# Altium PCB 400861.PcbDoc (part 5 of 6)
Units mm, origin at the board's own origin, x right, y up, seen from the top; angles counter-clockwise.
Board outline 145 x 63.5 mm, 8 copper layers (Top Side, Mid-Layer 1, Mid-Layer 2, Mid-Layer 3, Mid-Layer 4, Mid-Layer 5, Mid-Layer 6, Bottom Side), stack 1.529 mm thick; 284 components, 233 nets, 1158 pads, 3522 vias.
Unrouted connection lines stored in the file: 1.
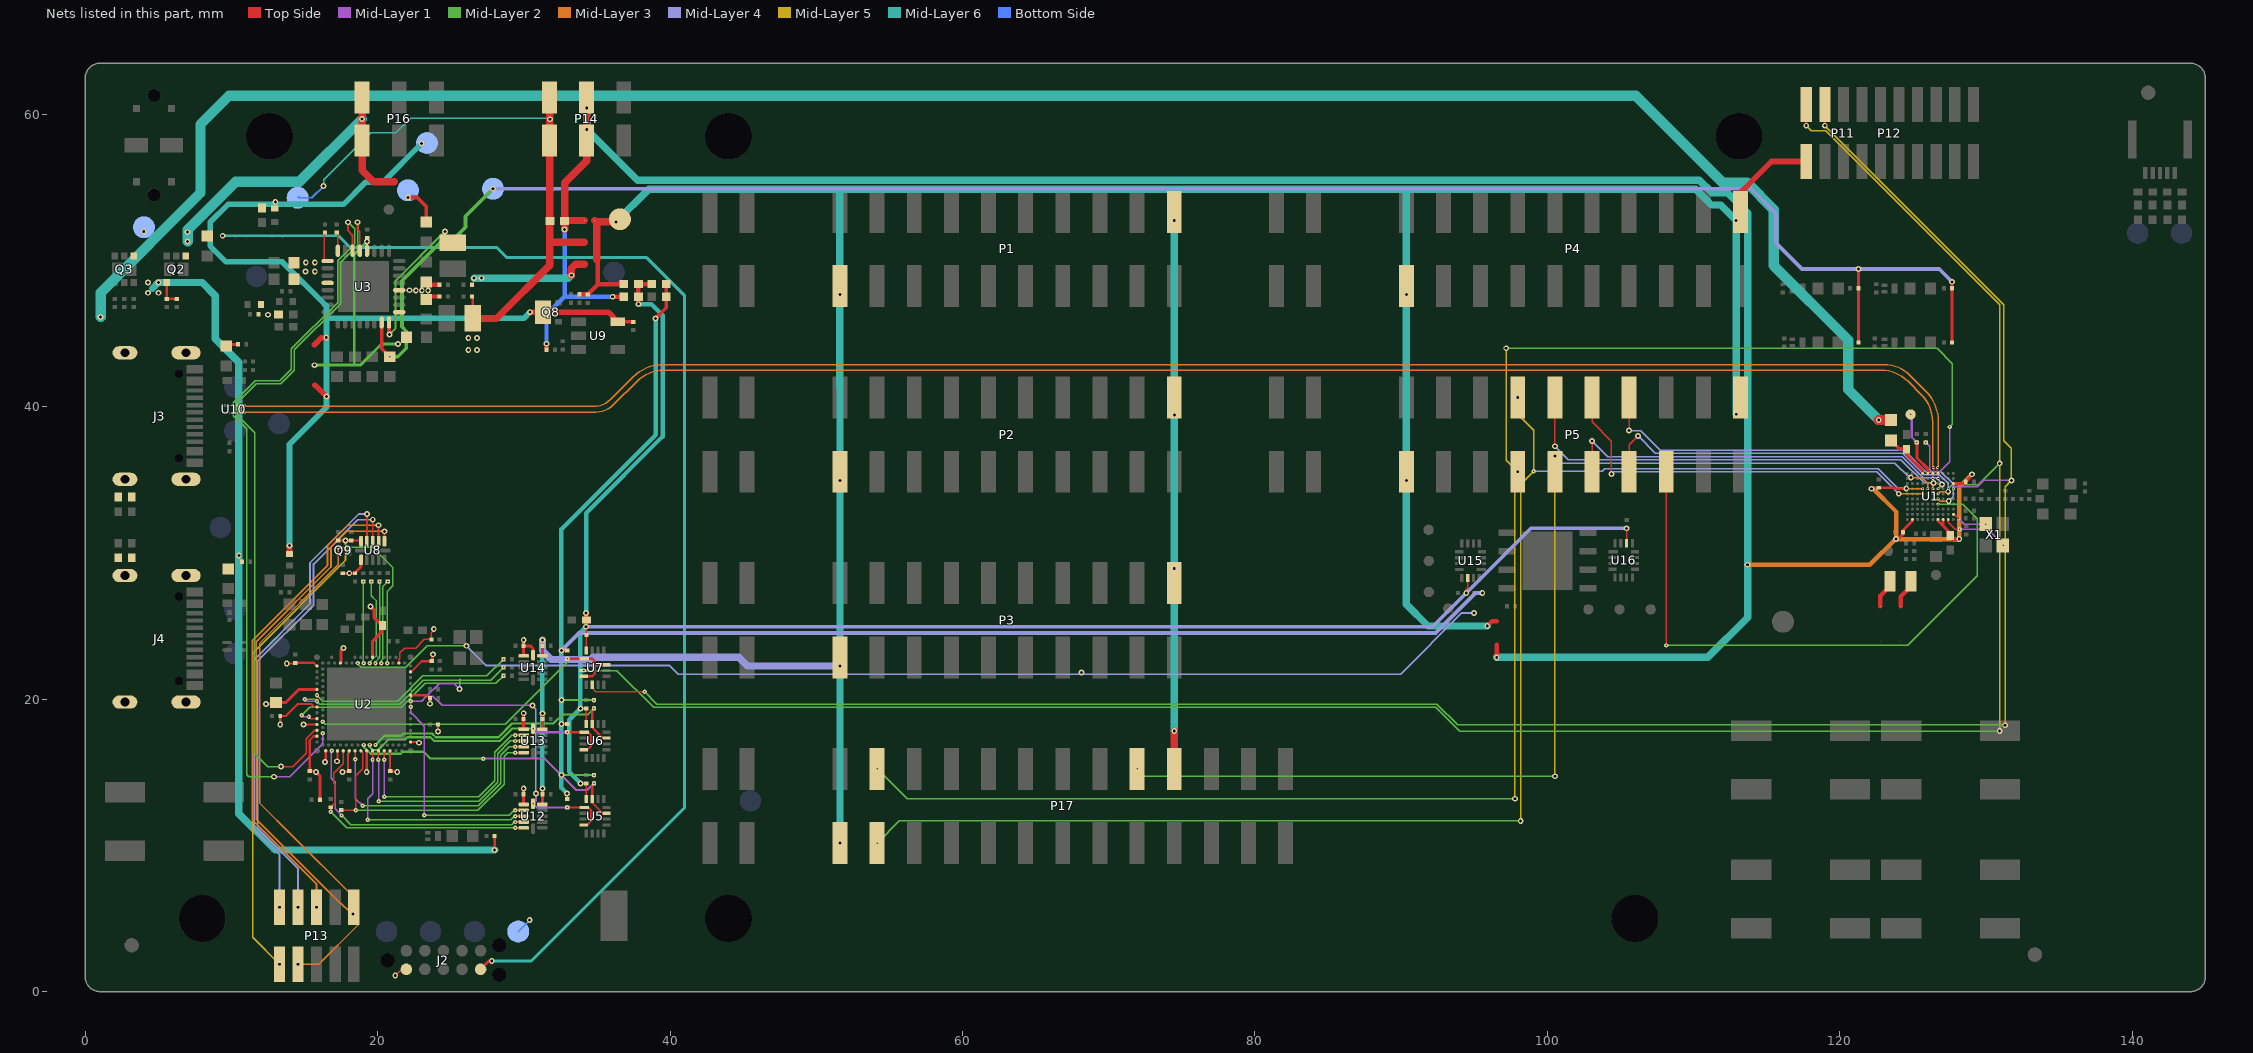
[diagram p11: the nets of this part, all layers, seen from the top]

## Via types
v1: diameter 0.4, hole 0.2, Top Side to Bottom Side, tented both sides, 2426 vias
v2: diameter 0.3, hole 0.1, Top Side to Mid-Layer 1, tented both sides, 299 vias
v3: diameter 0.4, hole 0.2, Mid-Layer 3 to Mid-Layer 4, tented both sides, 197 vias
v4: diameter 0.3, hole 0.1, Mid-Layer 1 to Mid-Layer 2, tented both sides, 197 vias
v5: diameter 0.3, hole 0.1, Mid-Layer 2 to Mid-Layer 3, tented both sides, 91 vias
v6: diameter 0.3, hole 0.1, Mid-Layer 4 to Mid-Layer 5, tented both sides, 81 vias
v7: diameter 0.3, hole 0.1, Mid-Layer 2 to Mid-Layer 3, 71 vias
v8: diameter 0.2, hole 0.1, Top Side to Mid-Layer 1, tented both sides, 64 vias
v9: diameter 0.2, hole 0.1, Mid-Layer 1 to Mid-Layer 2, tented both sides, 41 vias
v10: diameter 0.2, hole 0.1, Mid-Layer 2 to Mid-Layer 3, 19 vias
v11: diameter 0.2, hole 0.1, Mid-Layer 2 to Mid-Layer 3, tented both sides, 14 vias
v12: diameter 0.3, hole 0.1, Mid-Layer 5 to Mid-Layer 6, tented both sides, 12 vias
v13: diameter 0.2, hole 0.1, Mid-Layer 1 to Mid-Layer 2, 4 vias
v14: diameter 0.3, hole 0.1, Top Side to Mid-Layer 1, tented top, 3 vias
v15: diameter 0.2, hole 0.1, Top Side to Mid-Layer 1, tented top, 2 vias
v16: diameter 0.225, hole 0.1, Mid-Layer 1 to Mid-Layer 2, tented both sides, 1 vias

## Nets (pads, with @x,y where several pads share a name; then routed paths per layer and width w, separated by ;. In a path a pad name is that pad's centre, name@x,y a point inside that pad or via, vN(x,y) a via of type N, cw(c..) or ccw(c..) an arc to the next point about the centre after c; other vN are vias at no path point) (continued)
P3.04: P5.7 P17.4 U1.J4 | length 114.9
  Top Side w0.1: P17.4@54.16,15.24 v2(54.16,15.243)
  Mid-Layer 1 w0.1: v8(126.72,35.1) 126.72,35.464 127.512,36.256 v4(127.512,38.624)
  Mid-Layer 2 w0.1: v2(54.16,15.243) 56.208,13.195 v5(97.781,13.195) ; v5(97.185,44.006) 126.657,44.006 127.708,42.955 127.708,38.821 v4(127.512,38.624)
  Mid-Layer 5 w0.1: v5(97.185,44.006) 97.185,36.35 v6(97.975,35.56) 97.781,35.366 v5(97.781,13.195)
  other v2: 97.975,35.56
  other v3: 97.781,13.195 97.975,35.56 97.185,44.006
  other v4: 54.16,15.243 97.975,35.56
  other v5: 97.975,35.56
  other v6: 97.781,13.195 97.185,44.006
P3.05: P5.8 P17.3 U1.G7 | length 101.7
  Top Side w0.1: P17.3@54.16,10.16 v2(54.166,10.16)
  Mid-Layer 2 w0.1: v2(54.166,10.16) 55.681,11.675 v6(98.177,11.675)
  Mid-Layer 3 w0.1: v3(124.55,34.419) 124.569,34.4 v11(125.67,34.4)
  Mid-Layer 4 w0.1: v6(99.065,35.603) 103.761,35.603 103.911,35.752 122.648,35.752 123.981,34.419 v3(124.55,34.419)
  Mid-Layer 5 w0.1: v6(97.975,40.64) 97.975,39.485 99.065,38.395 v6(99.065,35.603) 98.177,34.715 v6(98.177,11.675)
  other v2: 97.975,40.64
  other v3: 98.177,11.675 97.975,40.64
  other v4: 54.166,10.16 97.975,40.64
  other v5: 98.177,11.675 97.975,40.64
  other v8: 125.67,34.4
  other v9: 125.67,34.4
P3.06: P5.9 P17.18 U1.G6 | length 77.4
  Top Side w0.1: P17.18@71.94,15.24 v2(71.94,15.242)
  Mid-Layer 2 w0.1: v2(71.94,15.242) 72.445,14.737 100.511,14.737 v5(100.515,14.733)
  Mid-Layer 3 w0.1: v3(124.858,35.157) 124.874,35.141 125.658,35.141 126.02,34.779 v8(126.02,34.4)
  Mid-Layer 4 w0.1: v3(100.515,36.645) 101.002,36.158 123.774,36.158 124.776,35.157 v3(124.858,35.157)
  Mid-Layer 5 w0.1: v5(100.515,14.733) v3(100.515,36.645)
  other v2: 100.515,36.645
  other v3: 100.515,14.733
  other v4: 71.94,15.242 100.515,36.645
  other v5: 100.515,36.645
  other v6: 100.515,14.733 100.515,36.645
  other v9: 126.02,34.4
  other v11: 126.02,34.4
P3.07: P5.10 U1.G5 | length 30.1
  Top Side w0.1: v1(100.513,37.306) 100.515,37.308 P5.10@100.515,40.05
  Mid-Layer 3 w0.1: v11(126.37,34.4) 126.37,34.749 v3(126.419,34.797)
  Mid-Layer 4 w0.1: v1(100.513,37.306) 101.44,36.38 124.18,36.38 125.762,34.797 v3(126.419,34.797)
  other v8: 126.37,34.4
  other v9: 126.37,34.4
P3.08: P5.11 U1.G4 | length 28.3
  Top Side w0.1: P5.11@103.055,34.97 v1@103.055,37.659
  Mid-Layer 3 w0.1: v8(126.72,34.4) 126.988,34.668 v3(126.988,34.691)
  Mid-Layer 4 w0.1: v1(103.055,37.659) 104.134,36.58 124.283,36.58 125.706,35.157 126.597,35.157 126.988,34.765 v3(126.988,34.691)
  other v9: 126.72,34.4
  other v11: 126.72,34.4
P3.09: P5.12 U1.F7 | length 27.2
  Top Side w0.1: P5.12@103.055,40.05 103.055,38.97 104.379,37.647 v1(104.379,35.397)
  Mid-Layer 3 w0.1: v3(124.034,34.058) 124.042,34.05 v11(125.67,34.05)
  Mid-Layer 4 w0.1: v1(104.379,35.397) 104.532,35.55 122.542,35.55 v3(124.034,34.058)
  other v8: 125.67,34.05
  other v9: 125.67,34.05
P3.10: P5.13 U1.F4 | length 27.2
  Top Side w0.1: P5.13@105.595,34.97 105.595,37.401 v1(106.211,38.017)
  Mid-Layer 3 w0.1: v11(126.72,34.05) 126.867,34.197 v3(127.417,34.197)
  Mid-Layer 4 w0.1: v1(106.211,38.017) 107.394,36.834 124.323,36.834 125.784,35.373 126.818,35.373 127.417,34.773 v3(127.417,34.197)
  other v8: 126.72,34.05
  other v9: 126.72,34.05
P3.11: P5.14 U1.E4 | length 27.5
  Top Side w0.1: v1(105.595,38.374) P5.14@105.595,40.05
  Mid-Layer 3 w0.1: v9(126.72,33.7) 126.871,33.55 v3(127.455,33.55)
  Mid-Layer 4 w0.1: v1(105.595,38.374) 106.388,38.374 107.724,37.039 124.417,37.039 125.878,35.577 126.916,35.577 127.767,34.725 127.767,33.862 v3(127.455,33.55)
  other v8: 126.72,33.7
  other v11: 126.72,33.7
P3.12: P5.15 U1.D4 | length 41.5
  Top Side w0.1: v2(108.135,23.68) P5.15@108.135,34.97
  Mid-Layer 2 w0.1: v2(108.135,23.68) 124.634,23.68 129.404,28.45 129.404,32.351 128.405,33.35 v9(126.72,33.35)
  other v4: 108.135,23.68
  other v8: 126.72,33.35
P5V0: C38.2 C59.1 FB5.2 Q8.3 R16.2 SB28.1 SB29.1 TP4.1 U9.5 | length 69.7
  Top Side w0.254: U9.5@36.433,45.816 C59.1@37.477,45.816
  Top Side w0.381: v1(13.968,30.503) 13.968,29.943 FB5.2@13.972,29.939 ; SB28.1@15.67,44.25 16.155,44.736 v1(16.483,44.736) ; 15.71,41.49 v1(16.5,40.7) ; v1(30.415,46.473) 35.776,46.473 U9.5@36.433,45.816
  Mid-Layer 6 w0.381: v1(13.968,30.503) 13.968,37.443 16.5,39.974 16.5,44.719 v1(16.483,44.736) 16.5,44.752 16.5,46.034 ; v1(23,58) 20.361,55.361 19.168,55.361 17.655,53.848 13.152,53.848 v1(13,54) 12.848,53.848 9.77,53.848 8.546,52.624 8.546,51 9.634,49.912 13.475,49.912 16.5,46.887 16.5,46.035 ; v1(30.415,46.473) 29.989,46.047 16.513,46.047 16.5,46.035
P5V0:LED: C52.2 R25.2 R26.2 R27.2 R28.2 TP1.1 U3.31 | length 130.8
  Top Side w0.203: R27.2@121.285,44.4 R25.2@121.285,48.1 121.285,49.367 cw(c121.366,49.367) v1@121.309,49.424 ; R28.2@127.685,44.4 R26.2@127.685,48.1 v1(127.684,48.552) v1(127.684,48.552)
  Top Side w0.254: U3.31@20.275,45.775 20.275,43.977 v2(20.825,43.427)
  Mid-Layer 2 w0.254: v2(20.825,43.427) 21.374,43.427 21.961,44.013 21.961,45.178 21.658,45.481 21.658,48.62 24.557,51.519 25.25,51.519 26.014,52.283 26.014,53.04 v1(27.889,54.915)
  Mid-Layer 4 w0.254: v1(27.889,54.915) 113.941,54.915 115.632,53.224 115.632,51.214 117.422,49.424 121.309,49.424 126.812,49.424 v1(127.684,48.552)
  other v1: 121.285,49.424
  other v4: 20.825,43.427
QSPI_CTRL: SB5.1 U2.B14 | length 79.7
  Mid-Layer 2 w0.1: v4(18.65,22.478) 18.65,22.408 18.883,22.175 21.912,22.175 23.393,23.657 v5(26.07,23.657)
  Mid-Layer 4 w0.127: v5(26.07,23.657) 27.429,22.298 39.963,22.298 40.55,21.711 68.132,21.711 89.967,21.711 94.158,25.903 v3(94.981,25.903)
  other v1: 68.132,21.831
  other v2: 18.65,22.478 94.981,25.903
  other v3: 26.07,23.657
  other v4: 94.981,25.903
  other v5: 94.981,25.903
Shield: C67.1 C68.1 C73.1 C74.1 J3.SHLD J4.SHLD
SWD0_CLK: R12.1 U2.B18 | length 5.9
  Top Side w0.106: R12.1@19.567,28.049 v4(19.567,28.052)
  Mid-Layer 2 w0.106: v4(19.45,22.475) 19.45,22.518 19.89,22.958 19.89,26.762 19.567,27.084 v4(19.567,28.052)
  other v2: 19.45,22.475 19.567,28.052
SWD0_CLK_EXT: P13.6 U8.8 | length 33.8
  Top Side w0.125: U8.8@20.064,30.816 v1(20.064,31.901)
  Mid-Layer 3 w0.125: v1(15.827,5.775) 15.827,7.354 11.431,11.75 11.431,24.002 16.564,29.135 16.564,30.496 17.97,31.901 v1(20.064,31.901)
SWD0_IO: R6.1 U2.B16 | length 5.6
  Top Side w0.106: R6.1@19.007,28.048 v4(19.007,28.05)
  Mid-Layer 2 w0.106: v4@19.007,28.053 19.007,22.519 v4(19.05,22.475)
  other v2: 19.05,22.475 19.007,28.05
SWD0_IO_EXT: P13.10 U8.7 | length 36.1
  Top Side w0.125: v1(18.3,5.3) P13.10@18.367,6.595 ; U8.7@20.464,30.816 20.464,31.473 v1(20.477,31.486)
  Mid-Layer 3 w0.125: 11.696,11.804 11.696,23.942 16.801,29.048 16.801,30.395 17.893,31.486 v1(20.477,31.486) ; 11.696,11.804 17.269,6.232 ; 17.269,6.231 ccw(c17.357,6.32) 17.273,6.228 v1(18.3,5.3)
SWD0_RESET: R47.1 U2.B22 | length 5.8
  Top Side w0.106: R47.1@20.689,28.051 v2(20.689,28.053)
  Mid-Layer 2 w0.106: v4(20.25,22.475) 20.25,22.65 20.338,22.739 20.338,27.703 v2(20.689,28.053)
  other v2: 20.25,22.475
  other v4: 20.689,28.053
SWD0_RESET_EXT: P13.2 U8.10 | length 33.8
  Top Side w0.125: v1(13.287,5.775) P13.2@13.287,6.595 ; U8.10@19.264,30.816 v1(19.264,32.67)
  Mid-Layer 4 w0.125: v1(13.287,5.775) 13.287,9.353 11.553,11.086 11.553,22.711 15.374,26.531 15.374,29.338 18.706,32.67 v1(19.264,32.67)
SWD0_SEL: P13.3 Q9.1 U2.B24 | length 47.1
  Mid-Layer 2 w0.106: v4(17.31,30.401) 19.654,30.401 21.036,29.019 21.036,27.759 20.65,27.373 v4(20.65,22.475)
  Mid-Layer 3 w0.106: v1(14.557,1.875) 15.975,1.875 18.663,4.564 18.663,6.167 18.037,6.793 ; v4(17.31,30.401) 17.31,29.205 15.802,27.698 13.529,25.425 11.922,23.818 11.922,12.909 14.233,10.598 18.036,6.795
  other v2: 20.65,22.475 17.31,30.401
  other v5: 17.31,30.401
SWD0_SWO: R13.1 U2.B20 | length 5.7
  Top Side w0.106: v2(20.128,28.051) R13.1@20.128,28.053
  Mid-Layer 2 w0.106: v4(19.85,22.475) 19.85,22.552 20.128,22.83 v4@20.128,28.053 ; v2(20.128,28.051) v4@20.136,28.043
  other v2: 19.85,22.475
  other v4: 20.128,28.051
SWD0_SWO_EXT: P13.4 U8.9 | length 33.8
  Top Side w0.125: v1(14.557,5.775) P13.4@14.557,6.595 ; U8.9@19.664,30.816 v1(19.664,32.283)
  Mid-Layer 4 w0.125: v1(14.557,5.775) 14.557,8.411 11.8,11.168 11.8,22.623 15.615,26.437 15.615,29.245 18.652,32.283 v1(19.664,32.283)
SWD3_CLK: R49.1 U2.R1 | length 15.7
  Mid-Layer 1 w0.1: v4(15,20) ccw(c15.125,20) 15.125,19.875 v2(15.85,19.875)
  Mid-Layer 2 w0.1: v4(15,20) 15.708,20 16.044,19.665 21.496,19.665 23.132,21.3 27.734,21.3 v4(28.608,22.174)
  other v2: 28.608,22.174
SWD3_CTRL: R40.2 U2.AB2 U7.1 U7.4 U7.11 | length 23.2
  Top Side w0.152: v4(32.956,22.767) 34.657,22.767 34.843,22.582 34.843,21.725 34.685,21.567 U7.4@34.095,21.567 ; 34.873,22.367 U7.11@35.645,22.367
  Mid-Layer 2 w0.1: v2(16.25,18.475) 16.425,18.3 28.738,18.3 32.956,22.519 v4(32.956,22.767)
  other v2: 32.956,22.767
  other v4: 16.25,18.475
SWD3_IO: R48.1 U2.N1 | length 14.1
  Mid-Layer 2 w0.1: v2(15.85,20.275) 16.255,19.87 21.361,19.87 23.083,21.593 27.469,21.593 v4(28.608,22.731)
  other v2: 28.608,22.731
  other v4: 15.85,20.275
SWD3_RESET: R50.1 U2.AA1 | length 16.1
  Top Side w0.1: v2(15.3,18.8) 15.425,18.675 U2.AA1@15.85,18.675
  Mid-Layer 1 w0.1: v4(14.8,18.9) 14.9,18.8 v2(15.3,18.8)
  Mid-Layer 2 w0.1: v4@14.819,18.881 v4(14.8,18.9) 15.363,19.464 21.604,19.464 23.238,21.097 28.088,21.097 v4(28.608,21.617)
  other v2: 28.608,21.617
SWDCLK: P11.4 P12.4 U1.G1 U7.6 | length 150
  Top Side w0.1: U7.6@34.67,20.992 34.67,20.772 34.93,20.512 v2(38.257,20.512) ; v1(118.977,59.228) P11.4@118.977,60.676
  Mid-Layer 1 w0.1: v15(127.77,34.4) 127.892,34.522 129.395,34.522 129.847,34.974 v1(131.736,34.974)
  Mid-Layer 2 w0.1: v2(38.257,20.512) 39.104,19.665 92.453,19.665 93.868,18.249 v5@131.315,18.249
  Mid-Layer 5 w0.1: v1(118.977,59.228) 131.232,46.973 131.232,37.687 131.735,37.184 v1(131.736,34.974) v1(131.736,34.974) 131.315,34.552 v5(131.315,18.224)
  other v3: 131.315,18.224
  other v4: 38.257,20.512
  other v6: 131.315,18.224
SWDIO: P11.2 P12.2 U1.G2 U7.3 | length 151.7
  Top Side w0.1: v1(117.707,59.228) P12.2@117.707,60.676
  Mid-Layer 2 w0.1: v4(34.095,21.967) 36.368,21.967 38.886,19.45 92.379,19.45 94.005,17.824 v5(130.938,17.824) ; v8(127.42,34.4) 127.696,34.675 129.474,34.675 v1(130.938,36.139)
  Mid-Layer 5 w0.1: v1(117.707,59.228) 118.06,58.875 119.029,58.875 130.938,46.967 v1(130.938,36.139) v5(130.938,17.824)
  other v2: 34.095,21.967
  other v3: 130.938,17.824
  other v6: 130.938,17.824
  other v13: 127.42,34.4
TRXTUNE: R2.2 U1.J5 | length 2.7
  Mid-Layer 1 w0.1: v2(125.874,37.566) 126.138,37.302 126.138,35.699 126.37,35.467 v8(126.37,35.1)
TWI0_SCL: U2.AF2 U3.14 | length 51.7
  Top Side w0.125: v1(17.975,52.625) 17.975,52.044 18.275,51.744 U3.14@18.275,50.675
  Mid-Layer 1 w0.1: v1(12.9,14.7) 14,14.7 16.25,16.95 v2(16.25,17.675)
  Mid-Layer 2 w0.1: v1(12.9,14.7) 11.3,14.7 cw(c11.3,14.96) 11.04,14.96 11.04,38.489 10.128,39.401 10.128,40.291 11.61,41.773 13.3,41.773 14.102,42.575 14.102,43.977 17.255,47.13 17.255,49.979 18.423,51.147 18.423,52.177 v1(17.975,52.625)
TWI0_SDA: U2.AE1 U3.13 | length 49.5
  Top Side w0.1: v1(13.4,15.4) 14.2,15.4 15.111,16.311 15.111,17.289 15.697,17.875 U2.AE1@15.85,17.875
  Top Side w0.125: v1(18.625,52.625) 18.625,52.139 18.775,51.989 U3.13@18.775,50.675
  Mid-Layer 2 w0.1: v1(13.4,15.4) 12.486,15.4 11.6,16.287 11.6,38.215 10.328,39.487 10.328,40.207 11.693,41.572 13.386,41.572 14.304,42.49 14.304,43.892 17.459,47.047 17.459,49.891 18.625,51.057 v1(18.625,52.625)
UART0_CTRL: R36.2 U2.R31 U5.1 U5.4 U12.12 | length 24.6
  Top Side w0.152: v2(32.956,12.606) 34.393,12.606 34.612,12.386 34.612,11.688 34.331,11.406 U5.4@34.095,11.406
  Mid-Layer 1 w0.1: v2(22.25,19.875) 22.998,19.875 23.332,20.21 ; v1(25.598,20.701) 25.224,21.075 24.198,21.075 23.332,20.21 ; v1(30.582,19.576) 24.405,19.576 23.771,20.21 23.332,20.21
  Mid-Layer 1 w0.152: v1(30.827,13.552) 30.827,13.054 v2(30.629,12.856) 30.879,12.606 v2(32.956,12.606)
  Mid-Layer 4 w0.1: v1(25.598,20.701) 25.598,21.396 ; v1(30.582,19.576) 30.827,19.331 v1(30.827,13.552)
UART0_CTS_DBGR: R9.1 U2.AL9 U12.5 | length 18.3
  Top Side w0.1: v2(16.8,12.3) R9.1@16.8,12.615 17.113,12.928 17.113,14.13 17,14.243 17,14.938 17.65,15.588 U2.AL9@17.65,16.475 ; v2(29.397,11.206) U12.5@29.989,11.206
  Mid-Layer 2 w0.1: v2(16.8,12.3) 17.895,11.206 v2(29.397,11.206)
  other v4: 29.397,11.206 16.8,12.3
UART0_HWFC: R19.2 U2.AK16 U5.11 U5.15 | length 20
  Top Side w0.152: v2(34.797,14.247) 34.67,14.12 U5.15@34.67,13.181 34.67,12.927 35.391,12.206 U5.11@35.645,12.206
  Mid-Layer 1 w0.152: v4(27.222,15.94) 31.432,15.94 33.579,13.793 34.342,13.793 v2(34.797,14.247)
  Mid-Layer 2 w0.152: v4(19.05,16.875) 19.05,16.741 19.522,16.269 21.584,16.269 21.718,16.404 23.157,16.404 23.621,15.94 v4(27.222,15.94)
  other v2: 19.05,16.875
UART0_RTS_DBGR: U2.AL5 U12.4 | length 17.5
  Top Side w0.1: v2(29.397,11.606) U12.4@29.989,11.606
  Mid-Layer 1 w0.1: v2(16.85,16.475) 16.809,16.434 16.809,14.584 17.085,14.308 17.085,12.497 v4(17.53,12.053)
  Mid-Layer 2 w0.1: v4(17.53,12.053) 18.162,11.421 29.181,11.421 29.366,11.606 v2(29.397,11.606)
  other v4: 29.397,11.606
UART0_RxD_DBGR: U2.AL19 U12.3 | length 15.6
  Top Side w0.1: v2(19.65,15.851) U2.AL19@19.65,16.475 ; v4(29.397,12.006) U12.3@29.989,12.006
  Mid-Layer 1 w0.1: v4(19.311,11.756) 19.311,13.211 19.65,13.55 19.65,15.482 v2(19.65,15.851)
  Mid-Layer 2 w0.1: v4(19.311,11.756) 29.089,11.756 29.338,12.006 v4(29.397,12.006)
  other v2: 29.397,12.006
UART0_TxD_DBGR: U2.U31 U12.2 | length 14.7
  Top Side w0.1: v4(29.397,12.406) U12.2@29.989,12.406
  Mid-Layer 1 w0.1: v2(22.25,19.475) 22.25,19.101 23.189,18.161 v4(23.189,12.067)
  Mid-Layer 2 w0.1: v4(23.189,12.067) 28.998,12.067 29.337,12.406 v4(29.397,12.406)
  other v2: 29.397,12.406
UART1_CTRL: R38.2 U2.AK18 U6.1 U6.4 U13.12 | length 17.7
  Top Side w0.152: v2(32.956,17.747) U6.1@34.145,17.746 34.397,17.746 34.599,17.545 34.599,16.805 34.34,16.546 U6.4@34.095,16.546
  Mid-Layer 1 w0.152: v2(30.629,17.996) 30.879,17.747 v2(32.956,17.747)
  Mid-Layer 2 w0.152: v2(19.45,16.875) 19.45,16.739 19.655,16.534 20.018,16.534 20.725,17.24 21.871,17.24 22.04,17.409 23.611,17.409 23.879,17.142 28.353,17.142 29.208,17.996 v2(30.629,17.996)
  other v4: 19.45,16.875 30.629,17.996
UART1_CTS_DBGR: R10.1 U2.AL15 U13.5 | length 19.6
  Top Side w0.1: R10.1@17.5,12.415 17.5,12.4 v2(18.503,12.4) 18.503,14.776 18.965,15.238 18.965,16.36 U2.AL15@18.85,16.475 ; v4(29.397,16.346) U13.5@29.989,16.346
  Mid-Layer 2 w0.1: v2(18.503,12.4) 26.859,12.4 28.656,14.198 28.656,16.105 28.898,16.346 v4(29.397,16.346)
  other v2: 29.397,16.346
  other v4: 18.503,12.4
UART1_HWFC: R37.2 U2.AK20 U6.11 U6.15 | length 18.8
  Top Side w0.152: v4(34.794,19.375) 34.67,19.25 U6.15@34.67,18.322 34.67,18.062 35.385,17.346 U6.11@35.645,17.346
  Mid-Layer 2 w0.152: v2(19.85,16.875) 20.473,17.498 21.596,17.498 21.761,17.663 23.718,17.663 23.977,17.404 28.259,17.404 29.193,18.338 32.015,18.338 32.627,18.95 34.37,18.95 v4(34.794,19.375)
  other v2: 34.794,19.375
  other v4: 19.85,16.875
UART1_RTS_DBGR: U2.AL13 U13.4 | length 17.8
  Top Side w0.1: U2.AL13@18.45,16.475 18.474,16.451 18.474,16.363 18.475,16.362 v2(18.475,15.9) ; v4(29.397,16.746) U13.4@29.989,16.746
  Mid-Layer 1 w0.1: v2(18.475,15.9) 18.475,13.213 v4(18.975,12.713)
  Mid-Layer 2 w0.1: v4(18.975,12.713) 26.878,12.713 28.433,14.268 28.433,16.188 28.992,16.746 v4(29.397,16.746)
  other v2: 29.397,16.746
UART1_RxD_DBGR: U2.AL21 U13.3 | length 16.2
  Top Side w0.1: v2(20.05,15.851) U2.AL21@20.05,16.475 ; v4(29.397,17.146) U13.3@29.989,17.146
  Mid-Layer 1 w0.1: v2(20.05,15.851) 20.069,15.832 v4(20.069,13.023)
  Mid-Layer 2 w0.1: v4(20.069,13.023) 26.903,13.023 28.219,14.338 28.219,16.284 29.081,17.146 v4(29.397,17.146)
  other v2: 29.397,17.146
UART1_TxD_DBGR: U2.AL23 U13.2 | length 15.6
  Top Side w0.1: v4(29.397,17.546) U13.2@29.989,17.546
  Top Side w0.125: v2(20.45,15.85) U2.AL23@20.45,16.475
  Mid-Layer 1 w0.1: v4(20.45,13.338) v2(20.45,15.85)
  Mid-Layer 2 w0.1: v4(20.45,13.338) 26.918,13.338 27.999,14.419 27.999,16.364 29.182,17.546 v4(29.397,17.546)
  other v2: 29.397,17.546
USB_nRF54_D+: U1.K5 U10.6 | length 122.2
  Top Side w0.099: U1.K5@126.37,35.45 ccw(c126.221,35.6) 126.432,35.6 126.432,35.754 ccw(c126.295,35.754) v8(126.392,35.851)
  Mid-Layer 3 w0.09: v2(10.643,39.639) 34.934,39.639 ; 34.947,39.639 34.934,39.639 ; v8(126.392,35.851) cw(c126.496,35.956) 126.349,35.956 126.349,39.001 ccw(c123.809,39.001) 125.605,40.797 124.634,41.768 ccw(c122.867,40) 122.867,42.5 39.537,42.5 ccw(c39.537,39.96) 37.741,41.756 36.111,40.126 cw(c34.934,41.304) 34.934,39.639
  other v4: 10.643,39.639
  other v9: 126.392,35.851
  other v10: 10.643,39.639
  other v11: 126.392,35.851
USB_nRF54_D-: U1.K4 U10.7 | length 122.8
  Top Side w0.099: v2(10.645,40.041) 10.645,40.089 U10.7@10.65,40.094 ; v8(126.699,35.851) ccw(c126.795,35.754) 126.658,35.754 126.658,35.6 ccw(c126.87,35.6) U1.K4@126.72,35.45
  Mid-Layer 3 w0.09: v2(10.645,40.041) 10.645,40.029 34.771,40.029 ccw(c34.771,41.687) 35.943,40.514 37.463,42.034 cw(c39.537,39.96) 39.537,42.893 123.029,42.893 cw(c123.029,40.393) 124.797,42.161 125.883,41.075 cw(c123.809,39.001) 126.742,39.001 126.742,35.956 cw(c126.594,35.956) v8(126.699,35.851)
  other v4: 10.645,40.041
  other v9: 126.699,35.851
  other v10: 10.645,40.041
  other v11: 126.699,35.851
VBUS: C34.2 C35.2 C55.2 J2.5 P16.1 Q2.4 Q3.4 R14.1 SB17.1 SB31.2 TP14.1 | length 110.4
  Top Side w0.2: J2.5@27.04,1.53 27.466,1.957 ; 27.553,2.043 27.466,1.957 ; v1(27.8,2.1) 27.61,2.1 27.466,1.957
  Top Side w0.5: P16.1@18.935,61.161 cw(c18.935,61.096) 19,61.096 18.935,61.031 P16.1@18.935,58.231 18.935,56.161 19.701,55.395 SB31.2@21.151,55.395
  Mid-Layer 6 w0.2: v1(9.4,51.7) 17.33,51.7 18.13,50.9 28.152,50.9 28.851,50.2 38.4,50.2 41,47.6 41,12.6 30.5,2.1 v1(27.8,2.1)
  Mid-Layer 6 w0.7: v1@7.009,51.305 7.009,51.947 7.009,52.119 10.285,55.394 14.643,55.394 v1(18.931,59.682)
  other v1: 12.5,46.3 7.002,51.298 7.002,51.947 4,52
VBUS:DBGR: C69.2 FB4.2 Q2.1 R5.2 R20.1 R21.1 | length 62.2
  Top Side w0.15: Q2.1@5.57,48.506 R20.1@5.57,47.391 R21.1@6.242,47.391 ; v1(28.003,9.685) R5.2@28.003,10.615
  Mid-Layer 6 w0.5: 4.6,48.1 v1(5,48.5) 8.004,48.5 8.9,47.604 8.9,44.654 10.5,43.054 10.5,12.175 12.989,9.685 v1(28.003,9.685)
  other v1: 10.502,29.827 4.3,47.8 5,47.8 4.3,48.5
VBUS:nRF: C63.2 FB3.2 R1.2 SB6.2 | length 146.7
  Top Side w0.106: FB3.2@9.635,44.147 FB3.2@9.763,44.275
  Top Side w0.2: FB3.2@9.763,44.275 C63.2@10.44,44.275
  Top Side w0.7: v1(122.666,39.098) R1.2@123.506,39.098
  Mid-Layer 6 w0.7: v1(1.052,46.152) 1.052,47.805 7.876,54.629 7.876,59.313 9.833,61.27 106.042,61.27 111.962,55.35 113.631,55.35 115.492,53.489 115.492,49.662 120.58,44.574 120.58,41.184 v1(122.666,39.098)
VBUS_5V0: C11.2 R1.1 U1.K7 | length 3.4
  Top Side w0.203: C11.2@124.568,37.101 124.568,36.765 125.67,35.663 U1.K7@125.67,35.45
  Top Side w0.254: R1.1@123.506,37.698 124.064,37.141 C11.2@124.528,37.141
VDD:DBGR: C15.1 C16.1 C17.1 C18.1 C21.1 C22.1 C23.1 C24.1 C26.1 C77.1 C79.1 C82.1 C85.1 C88.2 J2.1 R7.2 R35.2 R39.2 TP7.1 U2.A19 U2.AC1 U2.AG1 U2.AJ31 U2.AL3 U2.AL7 U2.AL11 U2.AL17 U2.AL25 U2.B8 U2.B28 U2.C1 U2.E31 U2.L1 U2.N31 U2.U1 U8.1 U12.1 U13.1 U14.1 U14.12 | length 45.3
  Top Side w0.1: v1(21.2,1.1) 21.511,1.411 21.841,1.411 J2.1@21.96,1.53 ; U2.B28@21.45,22.475 21.45,22.704 21.513,22.767 21.513,23.177 21.836,23.5 22.6,23.5 23.19,24.091 C24.1@23.668,24.091 23.668,24.548 23.839,24.719 v1(23.839,24.806)
  Top Side w0.15: v1(13.339,18.275) C15.1@13.339,18.854 13.714,18.854 14.536,19.675 15.463,19.675 15.663,19.475 U2.U1@15.85,19.475 ; v1(14.925,18.275) U2.AC1@15.85,18.275 ; C16.1@15.35,15.085 15.35,17.2 15.625,17.475 U2.AG1@15.85,17.475 ; C16.1@15.426,15.085 15.724,15.085 v1(15.774,15.035) ; v1(16.409,15.7) 16.45,15.7 U2.AL3@16.45,16.475 ; v1(17.209,15.763) ccw(c17.1,15.866) 17.25,15.866 U2.AL7@17.25,16.475 ; v1(17.599,15.035) 17.624,15.06 C17.1@18.022,15.06 ; U2.AL11@18.05,16.475 18.026,16.38 cw(c17.65,16.475) 17.984,16.28 ccw(c18.113,16.203) 17.963,16.204 17.963,15.286 ccw(c18.113,15.286) 18.007,15.18 18.042,15.145 C17.1@18.074,15.113 ; v1(19.25,15.025) U2.AL17@19.25,16.475 ; C21.1@20.85,15.035 C21.1@20.85,15.085 U2.AL25@20.85,16.475 ; 21.085,15.085 21.1,15.085 ; U2.AJ31@22.25,17.075 22.588,17.075 cw(c22.588,16.925) 22.621,17.072 v1(22.825,17.025) ; U2.N31@22.25,20.275 23.364,20.275 C22.1@23.573,20.067 23.574,20.066 23.574,19.699 v1(23.57,19.695) ; U2.E31@22.25,21.875 22.292,21.875 23.017,22.6 23.69,22.6 C23.1@23.7,22.61 ; v1(24.135,17.796) R7.2@24.135,18.275
  Top Side w0.152: v1(13.783,22.443) 14.302,22.443 C77.1@14.35,22.49 15.635,22.49 U2.C1@15.85,22.275
  Top Side w0.187: U2.B8@17.45,22.475 17.493,22.518 17.493,23.347 v1(17.653,23.508) ; v1@17.692,23.47 v1@17.73,23.508
  Top Side w0.2: v1(12.372,19.675) 12.75,19.675 C26.1@13.05,19.768 13.689,19.768 14.597,20.675 U2.L1@15.85,20.675 ; v1(15.774,15.035) 16.045,14.765 R35.2@16.045,13.125 R35.2@16,13.17
  Top Side w0.203: R39.2@17.601,28.619 v1(18.061,28.619) C88.2@18.452,28.62 ; C88.2@18.452,28.62 18.452,28.655 18.864,29.067 U8.1@18.864,29.536 ; C21.1@20.85,15.085 20.875,15.06 21.313,15.06 v1(21.338,15.035) ; C23.1@23.7,22.61 23.704,22.61 23.738,22.644 23.738,23.038 v1(23.775,23.075) ; v1(29.987,13.903) C79.1@29.987,13.515 U12.1@29.989,12.806 U12.1@29.989,12.806 ; U13.1@29.989,17.946 C82.1@29.988,18.654 v1(29.988,19.042) ; U14.1@29.989,22.967 C85.1@29.989,23.655 ; v1(29.989,24.043) C85.1@29.989,23.655 ; U14.12@30.629,23.017 30.629,23.465 30.438,23.655 C85.1@29.989,23.655
  Top Side w0.225: v1(19.5,26.35) 19.775,26.075 19.775,25.575 C18.1@20.325,25.025 ; U2.A19@19.65,22.875 19.65,23.97 20.25,24.57 C18.1@20.25,25.025
  Mid-Layer 6 w0.305: v1(29.987,13.903) v1(29.987,13.903)
  Bottom Side w0.1: TP7.1@29.616,4.115 v1(30.398,4.897)
VDD:IO: C80.1 C83.1 C86.1 P1.1 P1.20 P2.1 P2.20 P3.1 P3.20 P4.1 P4.20 P5.1 P5.20 P11.1 P12.1 P17.1 P17.20 R42.1 R52.2 R53.2 SB19.1 SB20.1 SB21.1 SB23.1 TP2.1 U12.11 U13.11 U14.11 | length 263
  Top Side w0.203: U12.11@31.269,12.806 C80.1@31.269,13.511 v1(31.269,13.899) ; U13.11@31.269,17.946 C83.1@31.269,18.651 v1(31.269,19.039) ; U14.11@31.269,22.967 C86.1@31.269,23.655 v1(31.269,24.043)
  Top Side w0.305: R52.2@33.799,47.693 34.352,47.693 R53.2@34.359,47.687 35.066,48.393 ; 34.975,50.05 35.066,49.959 35.066,48.393 ; R42.1@36.835,48.393 35.066,48.393 ; v1(95.889,25.009) 96.218,25.338 SB23.1@96.541,25.338
  Top Side w0.4: P4.20@113.215,52.75 P4.20@113.215,53.34 113.215,54.665 115.326,56.776 P11.1@117.707,56.776
  Top Side w0.5: SB19.1@34.85,52.75 34.95,52.65 ; 34.975,50.05 34.975,52.625 34.95,52.65 ; v1(36.3,52.65) 34.95,52.65 ; v1(51.621,10.161) P17.1@51.621,10.186 ; P17.20@74.353,15.24 74.48,15.367 v1(74.48,17.83)
  Mid-Layer 4 w0.5: v1(31.269,24.043) 31.269,23.318 31.868,22.719 34.585,22.719 34.734,22.869 44.688,22.869 45.287,22.27 v1(51.62,22.27)
  Mid-Layer 6 w0.305: v1(31.269,13.899) v1(31.269,19.039) v1(31.269,24.043)
  Mid-Layer 6 w0.5: v1(36.3,52.65) 38.531,54.881 51.489,54.881 ; v1@51.62,10.16 v1(51.62,22.27) v1(51.62,34.97) 51.596,47.669 51.596,54.774 51.489,54.881 ; v1@74.48,17.804 v1(74.48,28.934) 74.48,39.435 v1(74.5,39.455) 74.48,39.475 v1(74.48,52.75) 74.48,54.838 74.523,54.881 ; v1(95.889,25.009) 91.842,25.009 90.355,26.496 v1(90.355,34.97) v1(90.355,47.67) 90.355,54.764 90.472,54.881 ; v1(112.921,39.494) 112.915,39.501 v1(112.915,52.75) 111.864,53.8 111.229,53.8 110.148,54.881 90.472,54.881 ; 51.489,54.881 74.523,54.881 ; 74.523,54.881 90.472,54.881
  other v1: 51.62,47.67
VDD:nRF: C1.1 C2.1 C4.2 C5.1 P14.2 R15.1 R43.1 R55.1 SB19.2 SB24.1 U1.A3 U1.A4 U1.A9 U1.G10 U1.H1 | length 185.8
  Top Side w0.2: v1(122.182,34.398) 122.25,34.466 C2.1@122.674,34.466 123.639,34.466 123.705,34.4 U1.G10@124.62,34.4 ; v1(123.849,30.951) 123.99,30.951 124.331,31.292 C5.1@124.331,31.414 ; C5.1@124.357,31.414 124.357,31.597 124.97,32.211 U1.A9@124.97,32.3 ; U1.H1@127.77,34.75 128.491,34.75 C1.1@128.618,34.877 129.048,35.307 v1(129.048,35.385)
  Top Side w0.203: U1.A4@126.72,32.3 126.72,32.194 127.07,31.844 ; U1.A3@127.07,32.3 127.07,31.844 ; C4.2@127.552,31.202 127.552,31.362 127.07,31.844
  Top Side w0.305: R55.1@31.547,43.916 v1(31.547,44.313) ; v1(36.075,47.531) R43.1@36.835,47.531 ; v1(96.541,22.866) SB24.1@96.541,23.738 ; C4.2@127.552,31.202 127.803,30.951 v1(128.174,30.951)
  Top Side w0.5: v1(32.787,52.129) R15.1@32.787,52.709 ; SB19.2@34.15,52.75 32.8,52.75 32.8,55.338 34.3,56.838 34.3,57.386 P14.2@34.293,58.231 ; P14.2@34.293,61.161 34.299,60.432 34.3,60.316 v1(34.3,58.97)
  Mid-Layer 3 w0.305: v1(113.7,29.199) 122.06,29.199 123.812,30.951 v1(123.849,30.951) ; v1(122.182,34.398) 122.29,34.398 123.849,32.84 v1(123.849,30.951) ; v1(129.048,35.385) 128.174,34.511 v1(128.174,30.951) v1(123.849,30.951)
  Mid-Layer 6 w0.5: v1(34.299,60.426) v1(34.3,58.97) 37.766,55.504 110.4,55.504 111.27,54.633 112.317,54.633 113.081,53.869 ; v1(96.541,22.866) 110.98,22.866 113.7,25.587 v1(113.7,29.199) 113.7,53.25 113.088,53.862
  Bottom Side w0.305: v1(31.547,44.313) 31.547,46.294 32.784,47.531 ; v1(32.787,52.129) 32.787,47.533 32.784,47.531 ; v1(36.075,47.531) 32.784,47.531
VDD:nRF_PMIC: C46.2 C47.2 C54.1 L5.1 P14.1 R15.2 SB20.2 SB27.1 SB30.1 TP5.1 U3.1 U3.12 | length 58.1
  Top Side w0.1: U3.12@19.275,50.675 v1(19.275,51.306) C54.1@19.275,51.565
  Top Side w0.15: C47.2@26.448,47.547 cw(c26.448,47.498) 26.497,47.498 L5.1@26.497,46.047
  Top Side w0.5: L5.1@26.497,46.047 28.134,46.047 31.76,49.674 31.76,52.684 R15.2@31.787,52.709 31.76,52.734 31.76,57.386 P14.1@31.753,58.231 31.76,59.076 31.76,60.316 P14.1@31.753,61.161 ; 31.768,51.25 SB20.2@34.15,51.25
  Mid-Layer 2 w0.2: v1(15.67,42.85) 18.418,42.85 ; v1(19.275,51.306) 18.4,50.431 18.4,42.868 18.418,42.85 ; v1(21.402,44.291) 20.253,44.291 18.812,42.85 18.418,42.85
  Mid-Layer 6 w0.1: v1(16.3,55.1) 16.3,55.459 cw(c16.4,55.459) 16.329,55.529 19.537,58.737 21.252,58.737 22.249,59.733 31.567,59.733 31.573,59.727 31.718,59.727 v1(31.775,59.669)
  Bottom Side w0.1: TP5.1@14.633,54.41 TP5.1@14.529,54.306 15.506,54.306 v1(16.3,55.1)
  other v1: 26.2,43.9 26.8,43.9 26.2,44.7 26.8,44.7
VDD:SW: C61.1 C62.1 C78.1 C81.1 C84.1 C87.2 R42.2 R43.2 R44.2 U5.16 U6.16 U7.16 U15.14 U16.14 | length 119.8
  Top Side w0.1: v1(34.256,24.958) 34.27,24.944 U7.16@34.27,23.342 ; U5.16@34.27,13.181 C78.1@34.27,14.247 ; U6.16@34.27,18.322 C81.1@34.27,19.375 ; v2(94.453,27.266) 94.453,27.518 94.55,27.616 U15.14@94.55,28.308 ; U16.14@105.423,30.67 v6(105.423,31.692)
  Top Side w0.203: v1(33.866,19.364) 33.876,19.375 C81.1@34.27,19.375 ; v1(33.874,14.247) C78.1@34.27,14.247
  Top Side w0.305: v1(34.256,24.958) v1(34.256,25.903) ; v1(37.835,47.02) R43.2@37.835,47.531 R42.2@37.835,48.393 R44.2@38.742,48.393
  Mid-Layer 4 w0.254: v1(34.256,24.958) 92.144,24.958 98.878,31.692 v6(105.423,31.692)
  Mid-Layer 6 w0.305: v1(33.874,14.247) 33.095,15.027 33.095,18.593 v1(33.866,19.364) 33.866,24.568 v1(34.256,24.958) ; v1(34.256,25.903) 34.256,32.736 39.486,37.965 39.486,46.259 38.725,47.02 v1(37.835,47.02)
  other v2: 105.423,31.692
  other v3: 94.453,27.266 105.423,31.692
  other v4: 94.453,27.266 105.423,31.692
  other v5: 94.453,27.266 105.423,31.692
VDD:SW_PU: R19.1 R36.1 R37.1 R38.1 R40.1 R44.1 R51.1 R56.2 | length 108.2
  Top Side w0.152: v1(32.57,18.315) 32.572,18.317 R38.1@32.956,18.317 ; v1(32.572,23.335) 32.575,23.337 R40.1@32.956,23.337 ; R36.1@32.956,13.176 v1(32.956,13.555)
  Top Side w0.254: v2(34.796,14.816) v2(34.796,14.816) ; v1(39.009,46.05) 39.742,46.782 R51.1@39.742,47.531 R44.1@39.742,48.393
  Mid-Layer 2 w0.152: v5(32.57,14.823) 32.577,14.816 v2(34.796,14.816) ; v5@32.57,19.944 v2(34.793,19.944)
  Mid-Layer 4 w0.254: v1(32.572,23.335) 33.765,24.527 92.351,24.527 95.087,27.262 v3(95.551,27.262)
  Mid-Layer 6 w0.152: v5(32.57,19.944) v5(32.57,19.944)
  Mid-Layer 6 w0.305: v1(32.956,13.555) 32.57,13.94 v5(32.57,14.823) v1(32.57,18.315) v5(32.57,19.944) 32.57,31.627 39.031,38.088 39.031,46.027 v1(39.009,46.05)
  other v2: 95.551,27.262
  other v3: 32.57,14.823 32.57,19.944
  other v4: 34.796,14.816 34.793,19.944 95.551,27.262
  other v5: 95.551,27.262
  other v6: 32.57,14.823 32.57,19.944
  other v12: 32.57,14.823 32.57,19.944
VDD:SWD0: C89.1 P13.1 R41.2 U8.11 | length 34
  Top Side w0.125: R41.2@17.305,30.866 v1(17.798,30.866) 18.813,30.866 U8.11@18.864,30.816
  Mid-Layer 5 w0.125: v1(13.287,1.875) 11.453,3.709 11.453,23.16 17.798,29.505 v1(17.798,30.866)
VDD_USB_3V3: C10.2 TP12.1 U1.K6 | length 4.5
  Top Side w0.203: v2(125.274,37.566) 125.274,36.509 126.02,35.763 U1.K6@126.02,35.45
  Mid-Layer 1 w0.152: v2(124.848,39.48) 124.918,39.409 124.918,37.922 v2(125.274,37.566)
VOUT2: C48.2 C49.2 L6.1 SB21.2 TP6.1 U3.32 | length 20.5
  Top Side w0.25: v1(22.074,54.318) 22.716,54.318 23.327,53.707 C48.2@23.327,52.635 C48.2@23.327,52.91
  Top Side w0.254: U3.32@20.775,45.775 20.775,44.975 v1(20.8,44.95)
  Top Side w0.5: v1(33.25,49) 33.25,49.457 33.543,49.75 SB21.2@34.15,49.75
  Mid-Layer 2 w0.15: v1(20.8,44.95) 21.228,45.378 21.228,48.628 v1(24.6,52)
  Mid-Layer 6 w0.5: v1(26.6,48.8) v1(27.1,48.8) 33.05,48.8 v1(33.25,49)
VSET1: R17.1 U3.17 | length 2
  Top Side w0.125: 16.342,51.775 16.342,50.056 16.423,49.975 U3.17@16.575,49.975
VSET2: R18.1 U3.16 | length 1.3
  Top Side w0.125: R18.1@17.2,51.915 17.275,51.84 U3.16@17.275,50.675
VSYS: C40.2 C41.2 C42.2 C43.2 C44.2 C45.2 SB18.2 U3.4 U3.20 | length 1.1
  Top Side w0.3: C40.2@23.527,47.547 24.092,47.547 ; C41.2@23.527,48.347 24.092,48.347
  other v1: 23.019,47.962 23.455,47.955 22.173,47.976 22.609,47.965 15.075,49.25 15.7,49.25 15.085,49.875 15.7,49.875
XC1: U1.A2 X1.1 | length 4.6
  Top Side w0.1: U1.A2@127.42,32.3 127.42,32.116 127.914,31.622 v2(128.204,31.622) ; v2(131.195,30.546) X1.1@131.207,30.546
  Mid-Layer 1 w0.1: v2(128.204,31.622) 130.12,31.622 v2(131.195,30.546)
XC2: U1.B1 X1.3 | length 2.5
  Top Side w0.1: U1.B1@127.77,32.65 127.835,32.65 v8(128.152,32.333)
  Mid-Layer 1 w0.1: v8(128.152,32.333) 128.509,31.976 v2(129.999,31.976)
XL1: SB1.2 X2.2 | length 2
  Top Side w0.3: SB1.2@124.172,26.35 124.172,27.03 124.878,27.736 X2.2@124.878,28.074
XL2: SB2.2 X2.1 | length 2.3
  Top Side w0.3: SB2.2@122.772,26.35 122.772,27.067 123.428,27.723 X2.1@123.428,28.074 X2.1@123.428,27.722
pads on no net: Fid1.0 Fid2.0 Fid3.0 H1. H2. H3. H4. H5. H6. J2.0 J2.6 J2.7 J2.8 J2.9 J3. J3.0 J3.A8 J3.B8 J4. J4.0 J4.A8 J4.B8 J5.0 J5.1 J5.3 J5.5 P1.13 P1.14 P1.15 P1.16 P1.17 P1.18 P4.14 P4.15 P4.16 P4.17 P4.18 P5.16 P5.17 P5.18 P6.3 P7.3 P8.3 P9.3 P10.3 P11.7 P11.8 P12.7 P12.8 P12.11 P12.13 P13.7 P13.8 P13.9 P16.2 P18.3 SW5.0 U2. U2.A1 U2.A21 U2.A31 U2.AD2 U2.AE31 U2.AG31 U2.AH2 U2.AJ1 U2.AK2 U2.AK4 U2.AK6 U2.AK8 U2.AK10 U2.AK12 U2.AK14 U2.AK22 U2.AK24 U2.AK26 U2.AK28 U2.AK30 U2.AL1 U2.AL31 U2.B10 U2.D2 U2.F2 U2.J1 U2.K2 U2.M2 U2.P2 U2.T2 U2.V2 U2.W1 U2.Y2 U3.9 U3.10 U3.11 U3.15 U3.18 U3.19 U3.25 U3.26 U3.27 U5.7 U5.12 U6.7 U6.12 U7.7 U7.12 U7.13 U7.14 U7.15 U10.4 U11.4 U14.5 U14.7

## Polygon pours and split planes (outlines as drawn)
GND on Top Side "Top_Layer-GND" (solid, remove dead copper, pour order 28): 0.02,-0.034 0.02,63.466 145,63.466 145,-0.034
Shield on Top Side "SHIELD_L01_P003" (solid, remove dead copper, pour order 3): 0,44.6 7.913,44.6 7.913,18.238 0,18.238
NetQ3_1 on Top Side "NONET_L-01_P-001" (solid, pour order 23): 0.552,47.256 0.552,48.731 2.23,48.731 2.23,47.256 0.788,47.256
VBUS:nRF on Top Side "VBUS_nRF" (solid, pour order 26): 9.485,43.622 9.275,43.831 9.275,44.42 8.894,44.8 1.126,44.8 0.556,45.371 0.556,46.91 1.625,46.91 1.625,45.828 1.752,45.7 9.225,45.7 10,44.925 10,43.825 9.796,43.622 9.785,43.622
VBUS:DBGR on Top Side "VBUS:DBGR_L01_P011" (solid, pour order 11): 9.387,28.587 9.387,29.863 9.75,30.225 10.7,30.225 10.85,30.075 10.85,29.275 10.65,29.075 10.185,29.075 10.185,28.587
NetC70_2 on Top Side "NETC111_2" (solid, pour order 7): 10,24.283 10,27.925 9.4,27.925 9.4,26.758 7.491,26.758 7.491,26.248 9.4,26.248 9.4,24.283
VBUS on Top Side "VBUS" (solid, pour order 0): 3.11,50.091 3.775,50.091 3.85,50.166 3.85,51.15 cw(c4,51.15) 4,51.3 6.5,51.3 cw(c6.5,51.14) 6.66,51.14 6.66,50.34 ccw(c6.909,50.34) 6.909,50.091 7.191,50.091 ccw(c7.191,50.3) 7.4,50.3 7.4,51.2 cw(c7.5,51.2) 7.5,51.3 9.3,51.3 cw(c9.3,51.1) 9.5,51.1 9.5,49.383 ccw(c10.71,49.383) 9.854,48.527 10.698,47.684 ccw(c11.14,48.126) 11.14,47.5 11.5,47.5 cw(c11.5,47.3) 11.7,47.3 11.7,46.289 ccw(c11.938,46.289) 11.938,46.05 13.409,46.05 ccw(c13.409,46.166) 13.525,46.166 13.525,46.506 ccw(c13.43,46.506) 13.43,46.6 12.4,46.6 cw(c12.4,46.735) 12.265,46.735 12.265,47.343 ccw(c11.637,47.343) 12.081,47.788 10.875,48.994 cw(c11.659,49.778) 10.55,49.778 10.55,51.85 ccw(c10.075,51.85) 10.075,52.325 3.903,52.325 ccw(c3.903,51.532) 3.11,51.532
NetC64_2 on Top Side "NETC111_2" (solid, pour order 6): 10,40.5 10,43.162 9.4,43.162 9.4,41.994 7.491,41.994 7.491,41.484 9.4,41.484 9.4,40.5
VBUS:DBGR on Top Side "VBUS_DBGR" (solid, pour order 21): 5.78,48.731 4.137,48.731 4,48.594 4,47.7 4.125,47.575 5.78,47.575 5.78,48.59
GND on Mid-Layer 6 "Mid_Layer6-GND" (solid, remove dead copper, pour order 27): -0.002,0.013 -0.002,63.512 145,63.512 145,0.013
VSYS on Mid-Layer 6 "VSYS_mid_6" (solid, pour order 17): 14.865,50.09 16.408,50.09 16.975,49.524 17.379,49.12 23.7,49.12 23.7,47.512 16.412,47.512 14.877,49.047
VBUS:DBGR on Mid-Layer 6 "VBUS_DBGR" (solid, pour order 24): 5.78,48.731 4.137,48.731 4,48.594 4,47.7 4.125,47.575 5.78,47.575 5.78,48.59
VBUS:DBGR on Mid-Layer 6 "VBUS:DBGR_L07_P025" (solid, pour order 25): 9.475,27.85 9.275,28.05 9.275,29.85 9.75,30.325 10.7,30.325 10.85,30.175 10.85,29.375 10.65,29.175 10.175,29.175 10,29 10,28.025 9.825,27.85
GND on Bottom Side "Bottom_Layer-GND" (solid, remove dead copper, pour order 10): 0,0 0,63.5 145,63.5 145,0
Shield on Bottom Side "SHIELD_L08_P004" (solid, remove dead copper, pour order 4): -0.002,45.341 7.913,45.341 7.913,18.238 0,18.238 0,18.229
GND on Mid-Layer 3 "Mid_Layer3-GND" (solid, remove dead copper, pour order 29): 0,0 0,63.5 145,63.5 145,0
VDD:DBGR on Mid-Layer 3 "NONET_L-01_P-001" (solid, pour order 14): 17.294,28.89 12.126,23.722 12.126,12.983 19.951,5.157 19.951,0.439 30.629,0.439 30.629,28.89
GND on Mid-Layer 2 "Mid_Layer2-GND" (solid, remove dead copper, pour order 15): 0,0 0,63.5 145,63.5 145,0
GND on Mid-Layer 5 "Mid_Layer5-GND" (solid, remove dead copper, pour order 16): 0,0 0,63.5 145,63.5 145,0
GND on Mid-Layer 1 "Mid_Layer1-GND" (solid, remove dead copper, pour order 13): 0,0 0,63.5 145,63.5 145,0
GND on Mid-Layer 4 "Mid_Layer4-GND" (solid, remove dead copper, pour order 12): 0,0 0,63.5 145,63.5 145,0

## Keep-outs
Top Side:
  region: 127.77,33.973 127.77,33.429 133.343,33.429 133.343,33.973
  region: 9.235,43.772 10.035,43.772 10.035,43.172 9.235,43.172
Mid-Layer 2:
  lines w0.6: 11.227,39.836 34.896,39.836 ; 34.767,39.836 ccw(c34.767,41.665) 36.06,40.372 37.644,41.955 cw(c39.44,40.159) 39.44,42.699 39.856,42.699 122.315,42.699 122.924,42.699 cw(c122.924,40.159) 124.72,41.955 125.693,40.982 cw(c123.586,38.874) 126.566,38.874 126.566,36.452 126.566,39.052
Mid-Layer 4:
  lines w0.6: 11.227,39.836 34.896,39.836 ccw(c34.896,42.104) 34.898,39.836 ; 34.767,39.836 ccw(c34.767,41.665) 36.06,40.372 37.644,41.955 cw(c39.44,40.159) 39.44,42.699 39.856,42.699 ; 39.856,42.701 122.249,42.701 ; 122.315,42.699 122.924,42.699 cw(c122.924,40.159) 124.72,41.955 125.693,40.982 cw(c123.586,38.874) 126.566,38.874 ; 126.566,36.452 126.566,39.052

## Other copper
Top Side:
  rectangle net GND: 125.92,33.594 126.47,34.15
  rectangle net GND: 6.915,42.27 8.85,43.087
  rectangle net GND: 6.915,35.654 8.85,36.47
  rectangle net GND: 1.356,31.9 4.075,33.128
  rectangle net GND: 1.356,30.375 4.068,31.625
  rectangle net GND: 6.915,27.034 8.85,27.85
  rectangle net GND: 6.915,20.418 8.85,21.234
  rectangle net ANT: 142.889,14.783 144.159,18.945
  rectangle net Shield: 1.72,33.525 3.72,35.495
  region net Shield: 3.71,29.979 1.71,29.979 1.71,28.009 3.71,28.009
  rectangle net NetR16_1: 11.375,51 12.55,52.9
  rectangle net NetR16_1: 10.75,51 13.022,52.15
  rectangle net VSYS: 13.675,48.325 14.65,51.9
  rectangle net VSYS: 13.222,51 14.65,52.15
  rectangle net P5V0: 11.375,53.3 14.65,54.45
  region net VOUT2: 22.927,53.01 cw(c22.965,53.01) 22.965,53.047 25.116,53.047 25.116,51.775 28.2,51.775 28.2,48.134 26.298,48.134 26.309,50.646 24.215,50.645 24.215,52.26 22.927,52.26
  region net VSYS: 21.475,48.125 21.475,47.825 21.905,47.825 cw(c21.905,47.315) 22.247,47.694 cw(c18.493,43.542) 22.916,46.972 23.727,46.972 23.727,48.922 22.916,48.922 cw(c20.351,50.765) 22.337,48.309 cw(c21.817,48.952) 21.817,48.125
  region net GND: 23.727,44.35 22.925,44.35 22.925,45.825 21.925,46.825 21.6,46.825 21.6,47.125 21.998,47.125 22.748,46.375 23.727,46.375
  region net GND: 21.4,48.85 22.04,48.85 22.74,49.55 23.727,49.55 23.727,51.366 22.923,51.366 22.923,50.272 21.805,49.118 21.4,49.118
  region net GND: 133.113,33.973 127.953,33.973 127.953,34.232 133.113,34.232
  region net GND: 133.2,33.216 127.42,33.217 127.42,33.436 133.2,33.436
  region net VDD:nRF_PMIC: 21.191,46.625 21.191,44.189 21.731,43.55 27.1,43.55 27.1,46.957 25.963,46.957 25.963,44.175 22.528,44.175 22.528,45.485 21.75,46.135 21.75,46.625
  pour cut-out: 9.237,28.391 9.237,28.091 10.337,28.091 10.337,28.391
  pour cut-out: 23.948,49.545 22.9,49.545 22.9,49.318 23.948,49.318
  pour cut-out: 23.948,49.508 23.948,51.695 23.721,51.695 23.721,49.508
  pour cut-out: 22.73,51.662 24,51.662 24,51.889 22.73,51.889
  pour cut-out: 22.7,52.21 22.7,50.022 22.927,50.022 22.927,52.21
  pour cut-out: 23.8,46.505 22.774,46.505 22.774,46.378 23.8,46.378
  pour cut-out: 23.853,44.937 23.853,46.416 23.726,46.416 23.726,44.937
  pour cut-out: 22.927,44.3 22.927,45.78 22.8,45.78 22.8,44.3
  pour cut-out: 22.905,45.845 21.925,46.825 21.824,46.725 22.805,45.744
  pour cut-out: 25.932,45.05 25.932,47.079 25.292,47.079 25.292,45.05
  pour cut-out: 22.849,46.476 22.099,47.226 21.998,47.125 22.748,46.375
  pour cut-out: 22.741,49.549 21.991,48.799 22.092,48.699 22.842,49.449
  pour cut-out: 22.763,50.237 22.013,49.487 22.09,49.411 22.84,50.161
  pour cut-out: 24.662,47.397 24.662,48.497 24.4,48.497 24.4,47.397
  pour cut-out: 26.314,47.397 26.314,48.497 26.052,48.497 26.052,47.397
  pour cut-out: 26.052,48.497 26.052,48.65 24.662,48.65 24.662,48.497
  pour cut-out: 26.052,47.244 26.052,47.397 24.662,47.397 24.662,47.244
  pour cut-out: 24.359,44.35 24.359,45.05 23.732,45.05 23.732,44.35
  region net NetC36_2: 13.9,48.125 13.9,47.2 13.9,46.05 14.725,46.05 14.725,46.925 15.625,47.825 16.625,47.825 16.625,48.125
  region net VSYS: 14.825,48.325 13.9,48.325 13.9,50.273 15.95,50.273 15.95,48.625 16.625,48.625 16.625,48.325
  pour cut-out: 27.325,23.63 27.325,23.43 27.258,23.43 27.258,23.63
Mid-Layer 2:
  pour cut-out: 58.263,40.808 58.431,40.808 58.431,40.33 58.252,40.33
  pour cut-out: 98.233,26.196 98.233,24.726 98.032,24.726 98.032,26.196
Multi-Layer:
  pour cut-out: 137.18,0.126 145.031,0.126 144.989,50.335 137.185,50.335

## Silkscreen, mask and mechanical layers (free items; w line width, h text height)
Top Overlay:
  drawing of 61 lines, arcs and shapes, not listed
  text "OFF" at 2.222,60.114 h1.5 r90
  text "NFC" at 133.182,58.531 h1.78
  text "VBUS" at 17.477,56.103 h1
  text "GND" at 20.077,56.096 h1
  text "5V0" at 22.601,56.097 h1
  text "GND" at 35.44,55.675 h1.52
  text "GND" at 42.564,55.028 h1.52
  text "01" at 53.639,55.028 h1.52
  text "03" at 55.999,55.028 h1.52
  text "05" at 58.538,55.028 h1.52
  text "07" at 61.115,55.028 h1.52
  text "09" at 63.616,55.028 h1.52
  text "VDDIO" at 72.488,55.029 h1.52
  text "GND" at 81.299,55.028 h1.52
  text "01" at 92.374,55.028 h1.52
  text "03" at 94.734,55.028 h1.52
  text "05" at 97.273,55.028 h1.52
  text "07" at 99.85,55.028 h1.52
  text "09" at 102.351,55.028 h1.52
  text "VDDIO" at 111.223,55.029 h1.52
  text "GND" at 50.221,55.009 h1.52
  text "GND" at 88.956,55.009 h1.52
  text "VDD nRF / CURRENT / MEASURE" at 30.392,54.644 h1.8 r90
  text "PMIC" at 13.539,53.879 h1.8
  text "POWER" at 8.654,53.322 h1.8 r90
  text "ON" at 2.221,53.155 h1.5 r90
  text "DEBUG IN / TRACE" at 119.422,52.3 h1.78
  text "LED0" at 117.085,48.761 h1.78
  text "LED1" at 123.435,48.761 h1.78
  text "PORT0" at 49.95,48.135 h1.78 r90
  text "PORT2" at 88.704,48.135 h1.78 r90
  text "VDDIO" at 48.928,45.654 h1.52
  text "VDDIO" at 87.663,45.654 h1.52
  text "00" at 53.427,45.647 h1.52
  text "02" at 56.017,45.647 h1.52
  text "04" at 58.521,45.647 h1.52
  text "06" at 61.066,45.647 h1.52
  text "08" at 63.611,45.647 h1.52
  text "GND" at 73.085,45.634 h1.52
  text "00" at 92.162,45.647 h1.52
  text "02" at 94.752,45.647 h1.52
  text "04" at 97.256,45.647 h1.52
  text "06" at 99.801,45.647 h1.52
  text "08" at 102.346,45.647 h1.52
  text "10" at 105.053,45.647 h1.52
  text "GND" at 111.82,45.634 h1.52
  text "5V0" at 41.602,45.624 h1.52
  text "5V0" at 80.337,45.624 h1.52
  text "LED2" at 117.085,45.136 h1.78
  text "LED3" at 123.435,45.136 h1.78
  text "GND" at 42.564,42.328 h1.52
  text "01" at 53.639,42.328 h1.52
  text "03" at 55.999,42.328 h1.52
  text "05" at 58.538,42.328 h1.52
  text "07" at 61.115,42.328 h1.52
  text "09" at 63.616,42.328 h1.52
  text "13" at 68.843,42.328 h1.52
  text "VDDIO" at 72.488,42.329 h1.52
  text "GND" at 81.299,42.328 h1.52
  text "01" at 92.374,42.328 h1.52
  text "03" at 94.734,42.328 h1.52
  text "05" at 97.273,42.328 h1.52
  text "07" at 99.85,42.328 h1.52
  text "09" at 102.351,42.328 h1.52
  text "VDDIO" at 111.223,42.329 h1.52
  text "GND" at 50.221,42.309 h1.52
  text "11" at 66.318,42.319 h1.52
  text "15" at 71.343,42.319 h1.52
  text "GND" at 88.956,42.309 h1.52
  text "11" at 105.053,42.319 h1.52
  text "00-15" at 49.95,35.435 h1.78 r90
  text "PORT3" at 88.704,35.435 h1.78 r90
  text "12" at 68.858,32.956 h1.52
  text "14" at 71.558,32.967 h1.52
  text "VDDIO" at 87.663,32.954 h1.52
  text "12" at 107.593,32.956 h1.52
  text "00" at 53.427,32.947 h1.52
  text "02" at 56.017,32.947 h1.52
  text "04" at 58.521,32.947 h1.52
  text "06" at 61.066,32.947 h1.52
  text "08" at 63.611,32.947 h1.52
  text "10" at 66.318,32.947 h1.52
  text "GND" at 73.085,32.934 h1.52
  text "00" at 92.162,32.947 h1.52
  text "02" at 94.752,32.947 h1.52
  text "04" at 97.256,32.947 h1.52
  text "06" at 99.801,32.947 h1.52
  text "08" at 102.346,32.947 h1.52
  text "10" at 105.053,32.947 h1.52
  text "GND" at 111.82,32.934 h1.52
  text "5V0" at 41.602,32.924 h1.52
  text "5V0" at 80.337,32.924 h1.52
  text "nRF54LM20 USB" at 4.05,32.05 h1.8
  text "VDD / IO" at 49.629,31.814 h1.52
  text "DEBUGGER USB" at 4.05,29.804 h1.8
  text "GND" at 42.564,29.628 h1.52
  text "23" at 61.115,29.628 h1.52
  text "25" at 63.616,29.628 h1.52
  text "27" at 66.246,29.639 h1.52
  text "29" at 68.705,29.639 h1.52
  text "31" at 71.205,29.629 h1.52
  text "VDDIO" at 72.488,29.629 h1.52
  text "GND" at 50.221,29.609 h1.52
  text "17" at 53.639,29.619 h1.52
  text "19" at 56.139,29.619 h1.52
  text "21" at 58.679,29.619 h1.52
  text "PORT1" at 49.95,28.712 h1.78 r90
  text "nRF54LM20" at 126.636,25.612 h1.78
  text "16-31" at 49.95,22.735 h1.78 r90
  text "GND" at 114.761,22.553 h1.4
  text "VDDIO" at 48.928,20.254 h1.52
  text "16" at 53.519,20.254 h1.52
  text "22" at 61.066,20.256 h1.52
  text "24" at 63.611,20.256 h1.52
  text "18" at 56.019,20.247 h1.52
  text "20" at 58.4,20.247 h1.52
  text "26" at 66.196,20.247 h1.52
  text "28" at 68.741,20.247 h1.52
  text "30" at 71.204,20.247 h1.52
  text "GND" at 73.085,20.234 h1.52
  text "5V0" at 41.602,20.224 h1.52
  text "BUTTON 0" at 113.323,19.18 h1.78
  text "BUTTON 1" at 123.584,19.18 h1.78
  text "GND" at 42.563,16.954 h1.52
  text "01" at 53.639,16.928 h1.52
  text "03" at 55.999,16.928 h1.52
  text "05" at 58.538,16.928 h1.52
  text "07" at 61.115,16.928 h1.52
  text "09" at 63.616,16.928 h1.52
  text "13" at 68.858,16.928 h1.52
  text "VDDIO" at 72.488,16.929 h1.52
  text "GND" at 50.221,16.909 h1.52
  text "11" at 66.318,16.919 h1.52
  text "15" at 71.398,16.919 h1.52
  text "17" at 76.478,16.898 h1.52
  text "19" at 79.018,16.908 h1.52
  text "21" at 81.558,16.898 h1.52
  text "RESET" at 2.01,14.968 h1.78
  text "DEBUGGER" at 18.227,11.671 h1.8
  text "Expansion" at 49.95,10.087 h1.27 r90
  text "BUTTON 2" at 113.323,9.681 h1.78
  text "BUTTON 3" at 123.584,9.681 h1.78
  text "VDDIO" at 48.928,7.554 h1.52
  text "12" at 68.858,7.556 h1.52
  text "14" at 71.398,7.567 h1.52
  text "00" at 53.427,7.547 h1.52
  text "02" at 56.017,7.547 h1.52
  text "04" at 58.521,7.547 h1.52
  text "06" at 61.066,7.547 h1.52
  text "08" at 63.611,7.547 h1.52
  text "10" at 66.318,7.547 h1.52
  text "GND" at 73.085,7.534 h1.52
  text "16" at 76.478,7.527 h1.52
  text "18" at 79.018,7.536 h1.52
  text "20" at 81.42,7.546 h1.52
  text "5V0" at 41.602,7.524 h1.52
  text "GND" at 34.771,7.252 h1.4
  text "DEBUG OUT" at 11.327,7.175 h1.78
  text "nRF54LM20-DK" at 86.113,7.113 h3
  text ".PCBNumber" at 97.818,2.307 h2.03
  text "GND" at 34.771,1.987 h1.4
  text ".PCBRevision" at 97.823,0.965 h1.52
